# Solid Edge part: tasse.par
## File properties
Author: administrator
Template: Normal.par
Last saved by: administrator
Revision: 1
Application: Solid Edge
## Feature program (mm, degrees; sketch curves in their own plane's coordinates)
sketch for "unnamed Protrusion 1" plane through (0, 0, 0) normal (0, 0, 1) x-axis (1, 0, 0)
extrude "unnamed Protrusion 1" add finite 80 along +normal
sketch for "unnamed RevolvedProtrusion 1" plane through (25.4, 0, 0) normal (1, 0, 0) x-axis (0, 1, 0)
revolve "unnamed RevolvedProtrusion 1" add finite about sketch line (-16.9981, 36.8704) -> (13.1926, 36.8704)
sketch for "unnamed Cutout 1" plane through (0, 0, 80) normal (0, 0, 1) x-axis (0, 1, 0)
extrude "unnamed Cutout 1" cut finite 75 along -normal
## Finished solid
Body 1: solid body, 6 faces, 6 edges, 0 vertices.
  Faces by surface: plane 3, cylinder 2, torus 1
  Edges by curve: circle 4, intersection 2
Bounding box of the edges (mm; curved faces can reach further): 60.000 x 60.000 x 80.000, from (-30, -30, 0) to (30, 30, 80).
Cylindrical faces by radius (mm): R27.5 x1, R30 x1
Toroidal faces (ring radius, tube radius in mm): R28.6685 r5.901 x1
Planar faces by outward normal: +z 2, -z 1
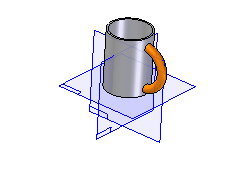
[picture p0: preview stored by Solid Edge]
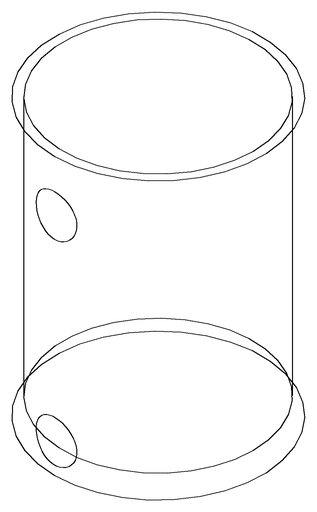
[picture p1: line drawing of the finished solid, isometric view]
